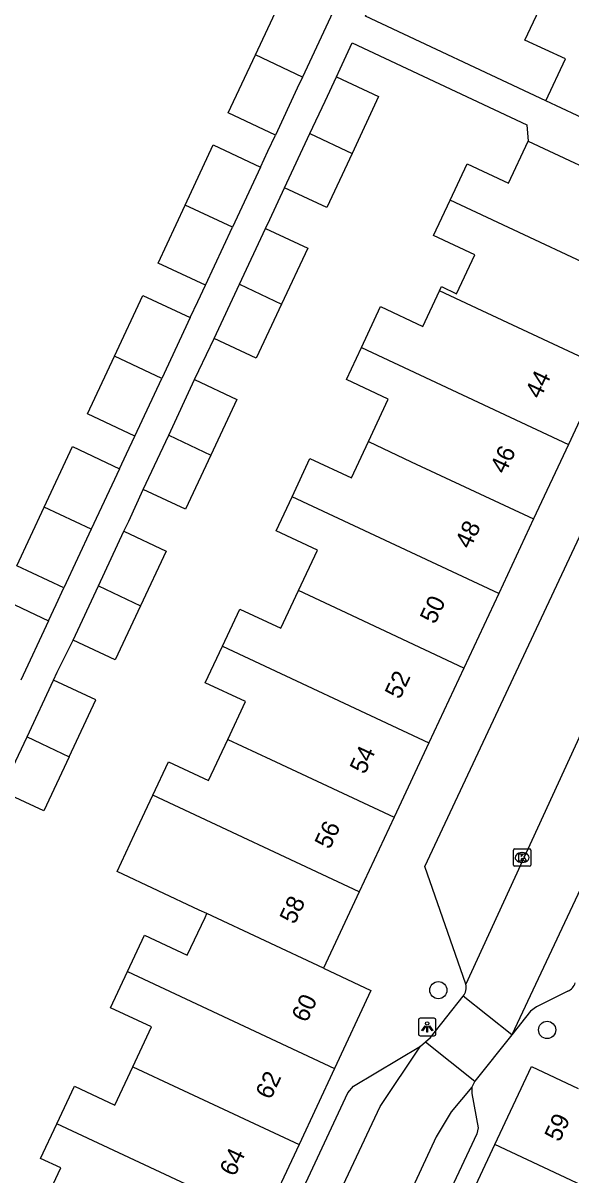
# Model space of a CAD drawing. Extents: x 159822 to 160765, y 380693 to 381634.
# Drawn here: x 160171.9 to 160203, y 381322.4 to 381387.8 of the extents above; entities that cross this region are included whole.
import ezdxf

# ---------------------------------------------------------------- set-up
doc = ezdxf.new("R2010")
doc.units = 0
for name, color, linetype in [('IMGEO_Boom', 7, 'Continuous'), ('IMGEO_Kolk', 7, 'Continuous'), ('IMGEO_Lichtpunt', 7, 'Continuous'), ('IMGEO_Pand', 7, 'Continuous'), ('IMGEO_Pand_nummerreeks', 7, 'Continuous'), ('IMGEO_Rijbaan_lokaal_open', 7, 'Continuous'), ('IMGEO_Voetpad_halfverhard', 7, 'Continuous'), ('IMGEO_Voetpad_open', 7, 'Continuous')]:
    doc.layers.add(name, color=color, linetype=linetype)

msp = doc.modelspace()

# ---------------------------------------------------------------- linework, layer by layer
at = {"layer": 'IMGEO_Boom'}
for centre in [(160195.472, 381332.904), (160201.652, 381330.647)]:
    msp.add_circle(centre, 0.489, dxfattribs=at)
at = {"layer": 'IMGEO_Kolk'}
for p, q in [((160199.808, 381340.936), (160200.66, 381340.936)), ((160199.733, 381340.01), (160199.733, 381340.862)), ((160200.221, 381340.716), (160200.246, 381340.716)), ((160200.734, 381340.862), (160200.734, 381340.01)), ((160200.66, 381339.936), (160199.808, 381339.936)), ((160200.244, 381340.156), (160200.219, 381340.156))]:
    msp.add_line(p, q, dxfattribs=at)
for points in [[(160199.808, 381340.936), (160200.66, 381340.936)], [(160199.733, 381340.01), (160199.733, 381340.862)], [(160200.054, 381340.636), (160200.177, 381340.636), (160200.177, 381340.485), (160200.307, 381340.636), (160200.471, 381340.636), (160200.325, 381340.485), (160200.478, 381340.236), (160200.326, 381340.236), (160200.241, 381340.4), (160200.177, 381340.333), (160200.177, 381340.236), (160200.054, 381340.236), (160200.054, 381340.636)], [(160200.734, 381340.862), (160200.734, 381340.01)], [(160200.66, 381339.936), (160199.808, 381339.936)]]:
    msp.add_lwpolyline(points, dxfattribs=at)
for centre, start, end in [((160199.81, 381340.86), 91.55205, 178.44795), ((160199.81, 381340.86), 91.55205, 178.44795), ((160200.658, 381340.86), 1.55205, 88.44795), ((160200.658, 381340.86), 1.55205, 88.44795), ((160199.81, 381340.012), 181.55205, 268.44795), ((160199.81, 381340.012), 181.55205, 268.44795), ((160200.658, 381340.012), 271.55205, 358.44795), ((160200.658, 381340.012), 271.55205, 358.44795)]:
    msp.add_arc(centre, 0.0765, start, end, dxfattribs=at)
for centre, major_axis, ratio, start_param, end_param in [((160200.22, 381340.436), (-0.387, 0.002), 0.722429, 4.712389, 7.853982), ((160200.245, 381340.436), (-0.39, 0.002), 0.717154, 1.570796, 4.712389)]:
    msp.add_ellipse(centre, major_axis=major_axis, ratio=ratio, start_param=start_param, end_param=end_param, dxfattribs=at)
at = {"layer": 'IMGEO_Lichtpunt'}
for p, q in [((160194.339, 381331.218), (160194.339, 381330.411)), ((160194.339, 381331.218), (160194.339, 381330.411)), ((160195.241, 381331.313), (160194.433, 381331.313)), ((160195.241, 381331.313), (160194.433, 381331.313)), ((160195.335, 381330.411), (160195.335, 381331.218)), ((160195.335, 381330.411), (160195.335, 381331.218)), ((160194.433, 381330.317), (160195.241, 381330.317)), ((160194.433, 381330.317), (160195.241, 381330.317))]:
    msp.add_line(p, q, dxfattribs=at)
for points in [[(160194.713, 381330.882), (160194.752, 381330.854), (160194.564, 381330.592), (160194.526, 381330.619), (160194.713, 381330.882)], [(160194.815, 381330.834), (160194.862, 381330.834), (160194.862, 381330.512), (160194.815, 381330.512), (160194.815, 381330.834)], [(160194.925, 381330.854), (160194.963, 381330.881), (160195.15, 381330.619), (160195.111, 381330.591), (160194.925, 381330.854)]]:
    msp.add_lwpolyline(points, dxfattribs=at)
msp.add_circle((160194.838, 381331.016), 0.0994, dxfattribs=at)
for centre, start, end in [((160194.433, 381331.218), 90, 180), ((160194.433, 381331.218), 90, 180), ((160195.241, 381331.218), 0, 90), ((160195.241, 381331.218), 0, 90), ((160194.433, 381330.411), 180, 270), ((160194.433, 381330.411), 180, 270), ((160195.241, 381330.411), 270, 0), ((160195.241, 381330.411), 270, 360)]:
    msp.add_arc(centre, 0.0946, start, end, dxfattribs=at)
at = {"layer": 'IMGEO_Pand'}
for points in [[(160185.072, 381386.012), (160187.195, 381390.554)], [(160187.195, 381390.554), (160189.88, 381389.298), (160187.754, 381384.75)], [(160201.582, 381383.397), (160202.696, 381385.776), (160200.395, 381386.853), (160201.367, 381388.93)], [(160186.216, 381381.46), (160183.534, 381382.722), (160185.072, 381386.012)], [(160187.754, 381384.75), (160185.072, 381386.012)], [(160187.754, 381384.75), (160187.457, 381384.115), (160186.216, 381381.46)], [(160188.177, 381381.543), (160189.035, 381383.378), (160189.682, 381384.761)], [(160189.682, 381384.761), (160192.079, 381383.64), (160190.571, 381380.417)], [(160211.011, 381378.985), (160206.483, 381381.104), (160204.259, 381382.144), (160201.582, 381383.397)], [(160186.734, 381378.458), (160188.177, 381381.543)], [(160188.177, 381381.543), (160190.571, 381380.417)], [(160181.084, 381377.48), (160182.684, 381380.902), (160185.365, 381379.64)], [(160196.142, 381377.759), (160197.106, 381379.819), (160199.453, 381378.721), (160200.575, 381381.119)], [(160200.575, 381381.119), (160203.204, 381379.889), (160205.428, 381378.849), (160209.956, 381376.73)], [(160190.571, 381380.417), (160189.13, 381377.337), (160186.734, 381378.458)], [(160185.365, 381379.64), (160183.765, 381376.218)], [(160195.534, 381372.615), (160195.644, 381372.849), (160196.505, 381372.447), (160197.541, 381374.661), (160195.204, 381375.755), (160196.142, 381377.759)], [(160207.872, 381372.274), (160196.142, 381377.759)], [(160182.235, 381372.943), (160179.548, 381374.192), (160181.084, 381377.48)], [(160183.765, 381376.218), (160181.084, 381377.48)], [(160182.235, 381372.943), (160183.765, 381376.218)], [(160184.173, 381372.985), (160185.653, 381376.149)], [(160185.653, 381376.149), (160188.049, 381375.028), (160186.564, 381371.852)], [(160182.731, 381369.901), (160184.173, 381372.985)], [(160184.173, 381372.985), (160186.564, 381371.852)], [(160177.073, 381368.898), (160178.686, 381372.349), (160181.373, 381371.1)], [(160191.1, 381369.395), (160192.187, 381371.717), (160194.588, 381370.594), (160195.534, 381372.615)], [(160204.893, 381368.234), (160197.962, 381371.478), (160195.534, 381372.615)], [(160186.564, 381371.852), (160185.127, 381368.78), (160182.731, 381369.901)], [(160181.373, 381371.1), (160179.755, 381367.64)], [(160191.493, 381364.05), (160192.621, 381366.459), (160190.246, 381367.57), (160191.1, 381369.395)], [(160191.1, 381369.395), (160202.861, 381363.891)], [(160178.224, 381364.363), (160175.541, 381365.621), (160177.073, 381368.898)], [(160179.755, 381367.64), (160177.073, 381368.898)], [(160204.893, 381368.234), (160202.861, 381363.891)], [(160178.224, 381364.363), (160179.755, 381367.64)], [(160180.147, 381364.42), (160181.621, 381367.571)], [(160181.621, 381367.571), (160184.017, 381366.45), (160182.537, 381363.285)], [(160178.705, 381361.336), (160180.147, 381364.42)], [(160180.147, 381364.42), (160182.537, 381363.285)], [(160187.158, 381360.917), (160188.175, 381363.091), (160190.529, 381361.99), (160191.493, 381364.05)], [(160191.493, 381364.05), (160193.929, 381362.91), (160200.88, 381359.658)], [(160202.861, 381363.891), (160200.88, 381359.658)], [(160173.07, 381360.333), (160174.675, 381363.767), (160177.357, 381362.509)], [(160182.537, 381363.285), (160181.101, 381360.215), (160178.705, 381361.336)], [(160177.357, 381362.509), (160175.752, 381359.075)], [(160187.518, 381355.588), (160188.597, 381357.894), (160186.256, 381358.99), (160187.158, 381360.917)], [(160198.899, 381355.424), (160187.158, 381360.917)], [(160174.197, 381355.748), (160171.514, 381357.006), (160173.07, 381360.333)], [(160175.752, 381359.075), (160173.07, 381360.333)], [(160200.88, 381359.658), (160198.899, 381355.424)], [(160175.752, 381359.075), (160174.197, 381355.748)], [(160176.159, 381355.869), (160177.603, 381358.958)], [(160177.603, 381358.958), (160180, 381357.837), (160178.547, 381354.732)], [(160169.066, 381351.768), (160169.246, 381352.153), (160165.484, 381353.917), (160166.273, 381355.602), (160170.034, 381353.839), (160170.639, 381355.134), (160173.321, 381353.876)], [(160174.716, 381352.785), (160176.159, 381355.869)], [(160176.159, 381355.869), (160178.547, 381354.732)], [(160183.206, 381352.445), (160184.187, 381354.542), (160186.518, 381353.452), (160187.518, 381355.588)], [(160196.917, 381351.189), (160189.946, 381354.452), (160187.518, 381355.588)], [(160198.899, 381355.424), (160196.917, 381351.189)], [(160178.547, 381354.732), (160177.112, 381351.664), (160174.716, 381352.785)], [(160173.321, 381353.876), (160171.748, 381350.511)], [(160183.508, 381347.143), (160184.514, 381349.292), (160182.23, 381350.36), (160183.206, 381352.445)], [(160183.206, 381352.445), (160194.936, 381346.956)], [(160196.917, 381351.189), (160194.936, 381346.956)], [(160172.098, 381347.284), (160173.606, 381350.509)], [(160174.486, 381346.145), (160176.003, 381349.388), (160173.606, 381350.509)], [(160170.656, 381344.2), (160172.098, 381347.284)], [(160172.098, 381347.284), (160174.486, 381346.145)], [(160179.246, 381343.976), (160180.135, 381345.876), (160182.416, 381344.808), (160183.508, 381347.143)], [(160183.508, 381347.143), (160185.948, 381346.001), (160192.955, 381342.722)], [(160194.936, 381346.956), (160192.955, 381342.722)], [(160174.486, 381346.145), (160173.052, 381343.079), (160170.656, 381344.2)], [(160182.31, 381337.25), (160181.887, 381337.448), (160177.215, 381339.636), (160178.214, 381341.771), (160179.246, 381343.976)], [(160190.973, 381338.487), (160179.246, 381343.976)], [(160192.955, 381342.722), (160190.973, 381338.487)], [(160190.973, 381338.487), (160188.941, 381334.144)], [(160177.811, 381333.958), (160178.776, 381336.02), (160181.204, 381334.884), (160182.212, 381337.039), (160182.31, 381337.25)], [(160188.941, 381334.144), (160182.31, 381337.25)], [(160178.108, 381328.56), (160179.163, 381330.813), (160176.847, 381331.897), (160177.811, 381333.958)], [(160177.811, 381333.958), (160189.573, 381328.457)], [(160188.941, 381334.144), (160191.642, 381332.878), (160189.573, 381328.457)], [(160173.791, 381325.318), (160174.79, 381327.453), (160177.087, 381326.378), (160178.108, 381328.56)], [(160178.108, 381328.56), (160180.701, 381327.347), (160187.554, 381324.142)], [(160198.686, 381324.132), (160200.76, 381328.565), (160203.421, 381327.319)], [(160189.573, 381328.457), (160187.554, 381324.142)], [(160172.867, 381320.363), (160174.016, 381322.82), (160172.873, 381323.355), (160173.791, 381325.318)], [(160185.534, 381319.826), (160173.791, 381325.318)], [(160187.554, 381324.142), (160185.534, 381319.826)], [(160196.663, 381319.809), (160198.686, 381324.132)], [(160210.378, 381318.659), (160210.143, 381318.769), (160198.686, 381324.132)]]:
    msp.add_lwpolyline(points, dxfattribs=at)
at = {"layer": 'IMGEO_Rijbaan_lokaal_open'}
for points in [[(160214.068, 381361.802), (160213.839, 381360.932), (160213.284, 381359.351), (160199.639, 381330.369)], [(160209.453, 381360.273), (160197.039, 381333.242)], [(160194.732, 381329.969), (160195.021, 381330.217), (160196.888, 381332.562)], [(160199.639, 381330.369), (160196.888, 381332.562)], [(160194.454, 381329.73), (160194.732, 381329.969)], [(160194.732, 381329.969), (160197.544, 381327.742)], [(160199.639, 381330.369), (160197.544, 381327.742)], [(160177.045, 381294.172), (160192.165, 381326.293), (160194.454, 381329.73)], [(160197.381, 381327.399), (160196.193, 381325.998), (160195.339, 381324.582), (160180.486, 381292.549)], [(160197.544, 381327.742), (160197.381, 381327.399)]]:
    msp.add_lwpolyline(points, dxfattribs=at)
msp.add_arc((160196.224, 381333.066), 0.834, 322.79867, 12.16156, dxfattribs=at)
at = {"layer": 'IMGEO_Voetpad_halfverhard'}
for points in [[(160201.582, 381383.397), (160191.323, 381388.201), (160191.965, 381389.574)], [(160189.682, 381384.761), (160189.893, 381385.212), (160190.583, 381386.687), (160200.506, 381382.042), (160200.575, 381381.119)], [(160185.365, 381379.64), (160185.79, 381380.55), (160186.216, 381381.46)], [(160185.653, 381376.149), (160185.89, 381376.655), (160186.734, 381378.458)], [(160181.373, 381371.1), (160181.8, 381372.013), (160182.235, 381372.943)], [(160181.621, 381367.571), (160181.864, 381368.091), (160182.731, 381369.901)], [(160177.357, 381362.509), (160177.754, 381363.358), (160178.224, 381364.363)], [(160177.603, 381358.958), (160177.875, 381359.54), (160178.705, 381361.336)], [(160173.321, 381353.876), (160173.75, 381354.793), (160174.197, 381355.748)], [(160173.606, 381350.509), (160173.815, 381350.955), (160174.716, 381352.785)]]:
    msp.add_lwpolyline(points, dxfattribs=at)
at = {"layer": 'IMGEO_Voetpad_open'}
for points in [[(160197.039, 381333.242), (160194.699, 381339.927), (160206.957, 381366.034), (160208.932, 381360.611)], [(160202.829, 381332.847), (160201.048, 381331.963), (160200.708, 381331.706), (160199.639, 381330.369)], [(160176.341, 381297.159), (160190.33, 381327.067), (160190.656, 381327.455), (160194.454, 381329.73)], [(160197.381, 381327.399), (160197.373, 381327.04), (160197.726, 381325.089), (160197.656, 381324.738), (160183.191, 381293.955)]]:
    msp.add_lwpolyline(points, dxfattribs=at)
msp.add_arc((160202.475, 381333.592), 0.825, 295.41946, 340.36308, dxfattribs=at)

# ---------------------------------------------------------------- texts
at = {"layer": 'IMGEO_Pand_nummerreeks'}
for s, rotation, p in [('44', 64.92324, (160201.263, 381366.423)), ('46', 64.92324, (160199.269, 381362.162)), ('48', 64.92324, (160197.276, 381357.903)), ('50', 64.92324, (160195.282, 381353.642)), ('52', 64.92324, (160193.286, 381349.374)), ('54', 64.92324, (160191.293, 381345.116)), ('56', 64.92324, (160189.299, 381340.854)), ('58', 64.92185, (160187.305, 381336.595)), ('60', 64.92185, (160187.988, 381331.016)), ('62', 64.92104, (160185.941, 381326.641)), ('59', 64.92366, (160202.357, 381324.238)), ('64', 64.92104, (160183.898, 381322.275))]:
    msp.add_text(s, height=1, rotation=rotation, dxfattribs=at).set_placement(p)

doc.saveas('drawing.dxf')
